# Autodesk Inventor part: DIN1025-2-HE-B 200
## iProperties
Created: 2006-03
Part Number: DIN1025-2-HE-B 200
Material: S 235 JRG2
Document SubType Name: Modeling
Designer: rgl
Density: 7.85 g/cm^3
Author: rgl
Abmessung: DIN1025-2-HE-B 200 ...100 lg
DIN/ASME: EN 10 025
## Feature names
1. Abgeleiteter Körper1 [Tagging]
